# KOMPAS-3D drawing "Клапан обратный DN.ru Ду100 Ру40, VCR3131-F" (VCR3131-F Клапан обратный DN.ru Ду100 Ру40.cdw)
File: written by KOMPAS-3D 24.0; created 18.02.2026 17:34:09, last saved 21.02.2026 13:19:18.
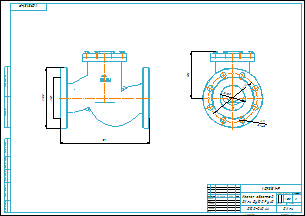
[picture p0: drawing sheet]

Document properties: art: D100-04044; Автор: R2D2; Форматы листов документа: A2; Полное имя файла: VCR3131-F Клапан обратный DN.ru Ду100 Ру40.m3d; Масса: 26.5; Наименование: Клапан обратный DN.ru Ду100 Ру40; Количество листов документа: 1; Примечание: D100-04044

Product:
- Part/product: Клапан обратный DN.ru Ду100 Ру40  | designation VCR3131-F
    Масса: 26.5
    Примечание: D100-04044
    additional columns: D100-04044

Views: Вид 1, Спереди, Проекционный вид 2
Referenced files in E:\Работа\Зайцев\VCR3131-F Клапан обратный DN.ru Ду15-300\DN100\: VCR3131-F Клапан обратный DN.ru Ду100 Ру40.m3d
Referenced files in E:\Работа\Зайцев\Для компаса\: чертеж DN.ru А3.cdt
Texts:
  VCR3131-F
  чертеж DN.ru А3.cdt
  Клапан обратный
  DN.ru Ду100 Ру40
  prop
  Клапан обратный DN.ru Ду100 Ру40
  VCR3131-F Клапан обратный DN.ru Ду100 Ру40
Dimensions and other numbers on the sheet: 0; 3; 2; 4; 180; 22; 8 отв.; 100; 190; 350; 235; 162; 1:2; 1; 26,5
